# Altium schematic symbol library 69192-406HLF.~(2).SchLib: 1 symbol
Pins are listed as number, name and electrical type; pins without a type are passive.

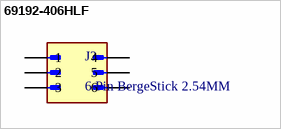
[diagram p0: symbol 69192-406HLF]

## 69192-406HLF
designator J?, comment 6 Pin BergeStick 2.54MM
6 Pin 3X3Pos THT S/T BergeStick 2.54MM Amphenol 69192-406HLF; MF: AMPHENOL ICC / FCI
footprint AMPHENOL_69192-406HLF
pins: 1, 2, 3, 4, 5, 6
